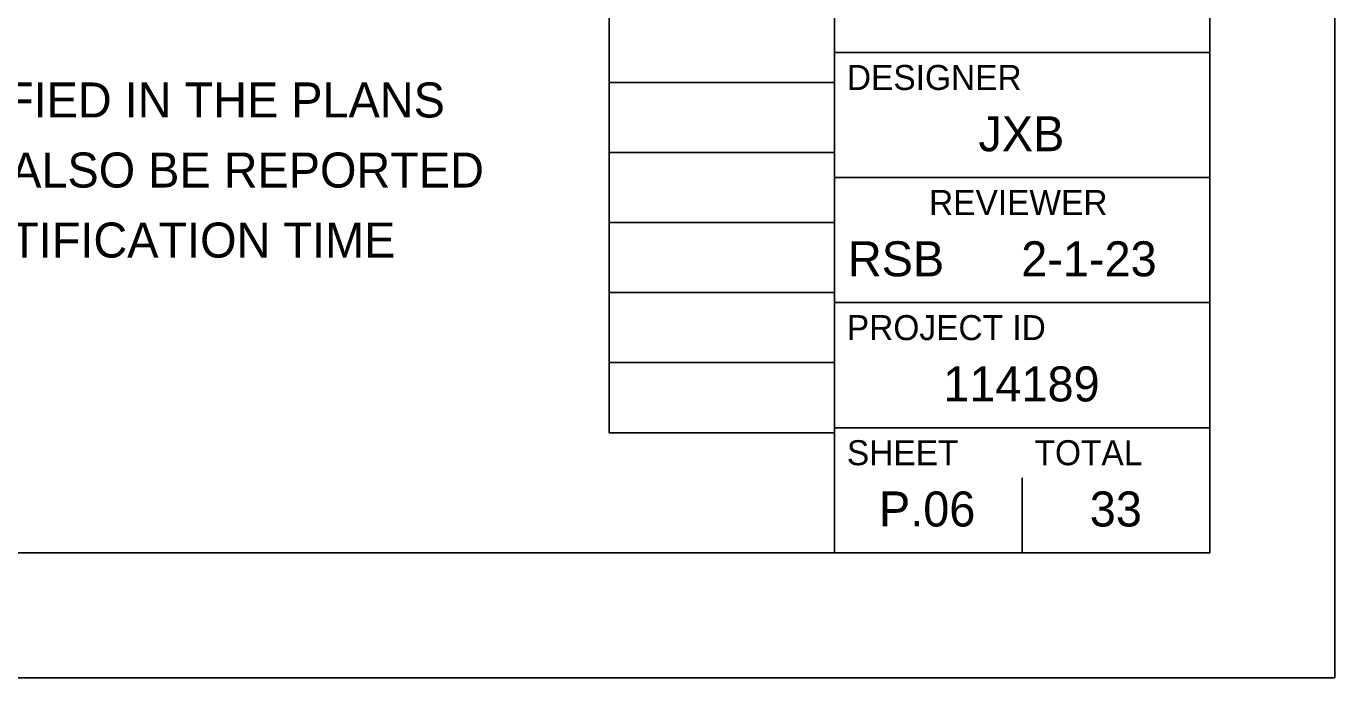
# Model space of a CAD drawing. Extents: x 0 to 34, y 0 to 22.
# Drawn here: x 28.77 to 34, y 0 to 2.61 of the extents above; entities that cross this region are included whole.
import ezdxf

# ---------------------------------------------------------------- set-up
doc = ezdxf.new("R2010")
doc.units = 0
for name, color, linetype in [('SH_Border', 7, 'Continuous'), ('SH_Cut_Line', 7, 'Continuous'), ('SH_Data', 7, 'Continuous'), ('SH_Text', 7, 'Continuous')]:
    doc.layers.add(name, color=color, linetype=linetype)

msp = doc.modelspace()

# ---------------------------------------------------------------- linework, layer by layer
at = {"layer": 'SH_Border'}
for p, q in [((32, 0.5), (32, 21.5)), ((32, 2.5), (33.5, 2.5)), ((32, 2), (33.5, 2)), ((32, 1.5), (33.5, 1.5)), ((32, 1), (33.5, 1))]:
    msp.add_line(p, q, dxfattribs=at)
msp.add_lwpolyline([(1.5, 21.5), (33.5, 21.5), (33.5, 0.5), (1.5, 0.5)], close=True, dxfattribs=at)
at = {"layer": 'SH_Cut_Line'}
msp.add_lwpolyline([(0, 0), (34, 0), (34, 22), (0, 22)], close=True, dxfattribs=at)
at = {"layer": 'SH_Data'}
for p, q in [((31.1, 0.98), (31.1, 21.14)), ((32, 0.98), (32, 21.14)), ((31.1, 2.38), (32, 2.38)), ((31.1, 2.1), (32, 2.1)), ((31.1, 1.82), (32, 1.82)), ((31.1, 1.54), (32, 1.54)), ((31.1, 1.26), (32, 1.26)), ((31.1, 0.98), (32, 0.98)), ((32.75, 0.5), (32.75, 0.8)), ((32.375, 0.675), (32.375, 0.675))]:
    msp.add_line(p, q, dxfattribs=at)

# ---------------------------------------------------------------- texts
for s, height, p in [('DESIGNER', 0.1, (32.05, 2.35)), ('JXB', 0.14, (32.5758, 2.105)), ('REVIEWER', 0.1, (32.3783, 1.85)), ('RSB', 0.14, (32.0541, 1.605)), ('2-1-23', 0.14, (32.7469, 1.605)), ('PROJECT ID', 0.1, (32.05, 1.35)), ('114189', 0.14, (32.4354, 1.105)), ('SHEET', 0.1, (32.05, 0.85)), ('TOTAL', 0.1, (32.8, 0.85)), ('P.06', 0.14, (32.1783, 0.605)), ('33', 0.14, (33.0207, 0.605))]:
    msp.add_text(s, height=height, dxfattribs=at).set_placement(p)
at = {"layer": 'SH_Text'}
for s, p in [('ANY UNFORESEEN CONDITIONS NOT SPECIFIED IN THE PLANS ', (24.66, 2.24)), ('REQUIRING TRAFFIC RESTRICTIONS SHALL ALSO BE REPORTED ', (24.66, 1.96)), ('TO THE PROJECT ENGINEER USING THE NOTIFICATION TIME ', (24.66, 1.68))]:
    msp.add_text(s, height=0.14, dxfattribs=at).set_placement(p)

doc.saveas('drawing.dxf')
